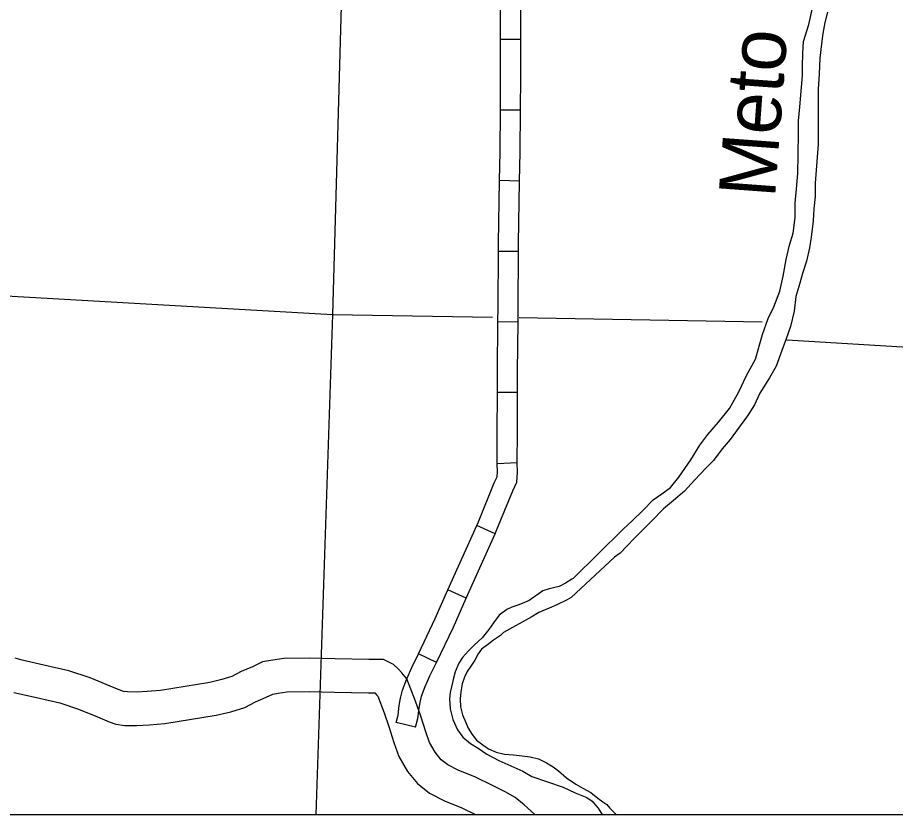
# Model space of a CAD drawing. Extents: x 1196286 to 1268366, y 2040822 to 2082115.
# Drawn here: x 1233701 to 1236164, y 2047966 to 2050201 of the extents above; entities that cross this region are included whole.
import ezdxf

# ---------------------------------------------------------------- set-up
doc = ezdxf.new("R2010")
doc.units = 0
for name, color, linetype in [('60', 7, 'Continuous'), ('61', 7, 'Continuous'), ('62', 7, 'Continuous'), ('Level 8', 7, 'Continuous'), ('Level 87', 7, 'Continuous')]:
    doc.layers.add(name, color=color, linetype=linetype)

msp = doc.modelspace()

# ---------------------------------------------------------------- linework, layer by layer
at = {"layer": '60'}
for points in [[(1234611.6, 2050334.4), (1234584.3, 2049368.5), (1234538.2, 2047966.3)], [(1233211.6, 2049446.5), (1234584.3, 2049368.5)], [(1234584.3, 2049368.5), (1235033.7, 2049360.7)], [(1235108.1, 2049359.4), (1235789.5, 2049347.6)], [(1235859.1, 2049296.8), (1236492, 2049259.3)]]:
    msp.add_lwpolyline(points, dxfattribs=at)
at = {"layer": '61'}
for p, q in [((1235112.7, 2050139.1), (1235056.4, 2050139.1)), ((1235111.8, 2049940.8), (1235055.6, 2049941.3)), ((1235109.5, 2049742.6), (1235053.3, 2049743.6)), ((1235106.4, 2049545), (1235050.2, 2049545.2)), ((1235105.2, 2049346.8), (1235048.9, 2049347.4)), ((1235103.5, 2049149.1), (1235047.2, 2049149.2)), ((1235102.7, 2048952.3), (1235046.5, 2048949.9)), ((1235040.8, 2048753.5), (1234989.5, 2048776.5)), ((1234960, 2048572.8), (1234908.7, 2048595.7)), ((1234876.2, 2048392.6), (1234825.5, 2048416.9)), ((1234818, 2048210.6), (1234763.5, 2048224.5))]:
    msp.add_line(p, q, dxfattribs=at)
for points in [[(1235112.7, 2050139.1), (1235112.7, 2050312.3), (1235105.9, 2050339.6), (1235104.9, 2050343.3)], [(1235056.4, 2050139.1), (1235056.5, 2050305.3), (1235053.5, 2050317.2)], [(1235055.6, 2049941.3), (1235056.4, 2050034.7), (1235056.4, 2050139.1)], [(1235111.8, 2049940.8), (1235112.6, 2050034.5), (1235112.7, 2050139.1)], [(1235053.3, 2049743.6), (1235054.6, 2049824.2), (1235055.6, 2049941.3)], [(1235109.5, 2049742.6), (1235110.9, 2049823.5), (1235111.8, 2049940.8)], [(1235050.2, 2049545.2), (1235050.3, 2049568), (1235053.3, 2049743.6)], [(1235106.4, 2049545), (1235106.5, 2049567.4), (1235109.5, 2049742.6)], [(1235048.9, 2049347.4), (1235049.4, 2049389.5), (1235050.2, 2049545.2)], [(1235105.2, 2049346.8), (1235105.6, 2049389.1), (1235106.4, 2049545)], [(1235047.2, 2049149.2), (1235047.4, 2049209.6), (1235048.9, 2049347.4)], [(1235103.5, 2049149.1), (1235103.6, 2049209.2), (1235105.2, 2049346.8)], [(1235046.5, 2048949.9), (1235046.4, 2048952), (1235047, 2049037.1), (1235047.2, 2049149.2)], [(1235102.7, 2048952.3), (1235102.7, 2048953), (1235103.2, 2049036.9), (1235103.5, 2049149.1)], [(1234989.5, 2048776.5), (1234994.2, 2048787.1), (1235038.6, 2048896.1), (1235046.2, 2048912.7), (1235047.4, 2048927.5), (1235046.5, 2048949.9)], [(1235040.8, 2048753.5), (1235046, 2048765), (1235090.3, 2048873.9), (1235101.4, 2048898.3), (1235103.8, 2048926.3), (1235102.7, 2048952.3)], [(1234908.7, 2048595.7), (1234989.5, 2048776.5)], [(1234960, 2048572.8), (1235040.8, 2048753.5)], [(1234825.5, 2048416.9), (1234872.8, 2048515.5), (1234908.7, 2048595.7)], [(1234876.2, 2048392.6), (1234923.8, 2048491.8), (1234960, 2048572.8)], [(1234763.5, 2048224.5), (1234768.7, 2048245.1), (1234771.7, 2048272.2), (1234775.3, 2048292.6), (1234781.1, 2048314.9), (1234792.8, 2048346.1), (1234806.9, 2048378.2), (1234825.5, 2048416.9)], [(1234818, 2048210.6), (1234824.2, 2048235), (1234827.4, 2048264.2), (1234830.3, 2048280.5), (1234834.8, 2048297.8), (1234845, 2048324.9), (1234858.1, 2048354.7), (1234876.2, 2048392.6)]]:
    msp.add_lwpolyline(points, dxfattribs=at)
at = {"layer": '62'}
for points in [[(1235973.2, 2050216.2), (1235966.1, 2050187), (1235960.2, 2050155.9), (1235956.2, 2050127), (1235951.9, 2050087.2), (1235949.4, 2050041.8), (1235946.6, 2049999.7), (1235946.6, 2049946.2), (1235946.8, 2049906.7), (1235946.6, 2049846.2), (1235939, 2049736.8), (1235938.9, 2049698.8), (1235935.1, 2049664.7), (1235933.2, 2049630.8), (1235927.4, 2049585.1), (1235922.6, 2049555.4), (1235914.2, 2049518), (1235903.3, 2049482.8), (1235895.6, 2049455.9), (1235884.3, 2049418.9), (1235879.3, 2049378), (1235869.7, 2049334.6), (1235856.9, 2049300.2), (1235844.9, 2049267), (1235829.3, 2049223.7), (1235810.6, 2049190.6), (1235783.7, 2049147.5), (1235768, 2049114.7), (1235748.9, 2049083.9), (1235725.3, 2049052), (1235700.6, 2049018), (1235678.2, 2048991.7), (1235653.1, 2048959.1), (1235632.8, 2048938.1), (1235599.7, 2048903.8), (1235571.7, 2048872.8), (1235541.1, 2048847.1), (1235513.5, 2048823.3), (1235479.4, 2048789), (1235450.9, 2048759.5), (1235431.4, 2048741.1), (1235410.6, 2048719), (1235391.8, 2048699.4), (1235375.4, 2048688.1), (1235254.3, 2048574.6)], [(1235259.9, 2048627.7), (1235400.4, 2048765.8), (1235425.3, 2048789.4), (1235455.6, 2048818.8), (1235484.1, 2048848.7), (1235508.4, 2048865.1), (1235532.9, 2048883.1), (1235556, 2048912.3), (1235589.4, 2048960.9), (1235615, 2049002.1), (1235637.1, 2049031.7), (1235667.1, 2049066.4), (1235698.4, 2049104.5), (1235724.9, 2049151), (1235745.8, 2049197.6), (1235771.6, 2049243), (1235791.1, 2049312.5), (1235806.7, 2049356.6), (1235822.9, 2049389.7), (1235839.6, 2049433.4), (1235848.4, 2049476.1), (1235857.3, 2049522.6), (1235866.8, 2049562.3), (1235876.6, 2049595.9), (1235882.8, 2049639.8), (1235882.2, 2049680.8), (1235886.4, 2049721), (1235890.4, 2049763.8), (1235891.2, 2049816.1), (1235891.8, 2049877.4), (1235891.8, 2049911.7), (1235896, 2049950.7), (1235902.8, 2050038.6), (1235903.4, 2050063.4), (1235903.8, 2050100.7), (1235906.1, 2050133.7), (1235920.6, 2050181.2), (1235930.2, 2050223.5)], [(1235259.9, 2048627.7), (1235256.4, 2048625.7), (1235238.3, 2048614.7), (1235220.5, 2048605.6), (1235192.3, 2048598.5), (1235175, 2048593.2), (1235158, 2048581.4), (1235149.7, 2048575.9), (1235136, 2048566), (1235123.2, 2048560.2), (1235107.8, 2048554.4), (1235087.4, 2048547.6), (1235073.8, 2048540.6), (1235052.6, 2048524.8), (1235036.6, 2048503.7), (1235023.5, 2048485.1), (1235004.1, 2048461.3), (1234994.6, 2048452.1), (1234981.6, 2048440.3), (1234966.1, 2048425.5), (1234949.7, 2048406.2), (1234938.9, 2048390.2), (1234928.8, 2048366), (1234923.7, 2048348), (1234918.4, 2048324.1), (1234915.2, 2048308), (1234913, 2048290), (1234915.2, 2048262.5), (1234921.9, 2048232.7), (1234935.7, 2048203.2), (1234950.7, 2048183.4), (1234971.4, 2048165.5), (1234993.3, 2048152), (1235018.1, 2048135), (1235051.2, 2048117.6), (1235085.4, 2048102.8), (1235118.9, 2048088), (1235144.2, 2048073), (1235232.1, 2048043.1), (1235265.5, 2048026.4), (1235298.3, 2048013.5), (1235312.7, 2048003.1), (1235316.4, 2047998.5), (1235329.7, 2047984.1), (1235337.7, 2047971.9), (1235340.8, 2047966.3)], [(1235254.3, 2048574.6), (1235240.8, 2048566.9), (1235214.4, 2048554.1), (1235192.5, 2048545.1), (1235163.1, 2048532.8), (1235141.9, 2048519.2), (1235064.8, 2048476.4), (1235055.7, 2048467.6), (1235036.8, 2048454.7), (1235023.1, 2048444.4), (1235002.3, 2048430.1), (1234993.5, 2048416.3), (1234983.9, 2048399.2), (1234973.1, 2048381.7), (1234962.8, 2048367.2), (1234954.7, 2048351.6), (1234948.4, 2048332.1), (1234944.3, 2048310), (1234943.2, 2048290.1), (1234944, 2048268), (1234949.3, 2048245.3), (1234958.3, 2048223.8), (1234965.5, 2048207.9), (1234976.5, 2048190.4), (1234988.3, 2048174.5), (1235006, 2048161.4), (1235022.7, 2048150.7), (1235043.9, 2048141.3), (1235067.4, 2048135.7), (1235092.5, 2048133), (1235116.8, 2048130.4), (1235139.2, 2048128.2), (1235162.4, 2048122.2), (1235184.7, 2048110.6), (1235203.6, 2048099.4), (1235218.4, 2048089), (1235241.3, 2048069.1), (1235266.9, 2048051.4), (1235287, 2048040.2), (1235309.2, 2048027.5), (1235328.8, 2048011.8), (1235342.9, 2048001.8), (1235354, 2047993.7), (1235362.9, 2047983.4), (1235380.2, 2047966.3)]]:
    msp.add_lwpolyline(points, dxfattribs=at)
at = {"layer": 'Level 8'}
msp.add_lwpolyline([(1241590.6, 2065596.8), (1214332.8, 2065596.8), (1214332.8, 2047966.3), (1241590.6, 2047966.3)], close=True, dxfattribs=at)
at = {"layer": 'Level 87'}
msp.add_line((1234985.5, 2047966.3), (1235152.1, 2047966.3), dxfattribs=at)
for points in [[(1235152.1, 2047966.3), (1235122.8, 2047992.9), (1235097.3, 2048013.8), (1235069.5, 2048029.7), (1235031.4, 2048048.2), (1234985.7, 2048070.6), (1234937.6, 2048090), (1234907.8, 2048105.1), (1234889.7, 2048119.7), (1234872.4, 2048140.6), (1234856.5, 2048167.8), (1234846.1, 2048197.6), (1234832.2, 2048241.9), (1234818, 2048283.6), (1234793.3, 2048346.3), (1234779.3, 2048363.3), (1234769, 2048374.5), (1234755.5, 2048386.4), (1234727.7, 2048400.8), (1234686.4, 2048401), (1234592.2, 2048402.8), (1234519.8, 2048404.7), (1234448.6, 2048403.4), (1234417.7, 2048398.8), (1234388.7, 2048393.9), (1234360.8, 2048380.6), (1234328.9, 2048367.2), (1234302.5, 2048353.2), (1234274.4, 2048344.3), (1234240.2, 2048336.3), (1234102.7, 2048314.2), (1234064.7, 2048310.9), (1234033.7, 2048309.3), (1234009.4, 2048309.7), (1233998.5, 2048311.2), (1233991.3, 2048313.6), (1233961.5, 2048326.3), (1233904.7, 2048349.7), (1233844.7, 2048369.4), (1233775, 2048385.2), (1233713.9, 2048399.1), (1233694.9, 2048404.2)], [(1233691.3, 2048308.1), (1233754.2, 2048293.8), (1233819.6, 2048279), (1233872.1, 2048261.7), (1233925.4, 2048239.8), (1233958.2, 2048225.9), (1233977, 2048219.6), (1234002.1, 2048216.1), (1234035.4, 2048215.5), (1234071.2, 2048217.4), (1234114.2, 2048221.1), (1234258.3, 2048244.3), (1234299.3, 2048253.8), (1234338.9, 2048266.4), (1234369.1, 2048282.4), (1234399.1, 2048295), (1234417.2, 2048303.6), (1234432.5, 2048306.2), (1234456.4, 2048309.8), (1234519.4, 2048310.9), (1234590, 2048309.1), (1234685.3, 2048307.2), (1234703.6, 2048307.2), (1234708.6, 2048301.7), (1234711.5, 2048298.2), (1234730, 2048251.3), (1234743.1, 2048212.9), (1234757.1, 2048168.1), (1234771, 2048128.4), (1234795.3, 2048086.7), (1234823.5, 2048052.7), (1234856.5, 2048026), (1234898.8, 2048004.6), (1234947.5, 2047984.9), (1234985.5, 2047966.3)]]:
    msp.add_lwpolyline(points, dxfattribs=at)

# ---------------------------------------------------------------- texts
at = {"layer": '62'}
msp.add_text('Meto', height=158.4, rotation=85.7799, dxfattribs=at).set_placement((1235825.8, 2049693))

doc.saveas('drawing.dxf')
